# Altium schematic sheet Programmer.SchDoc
size A
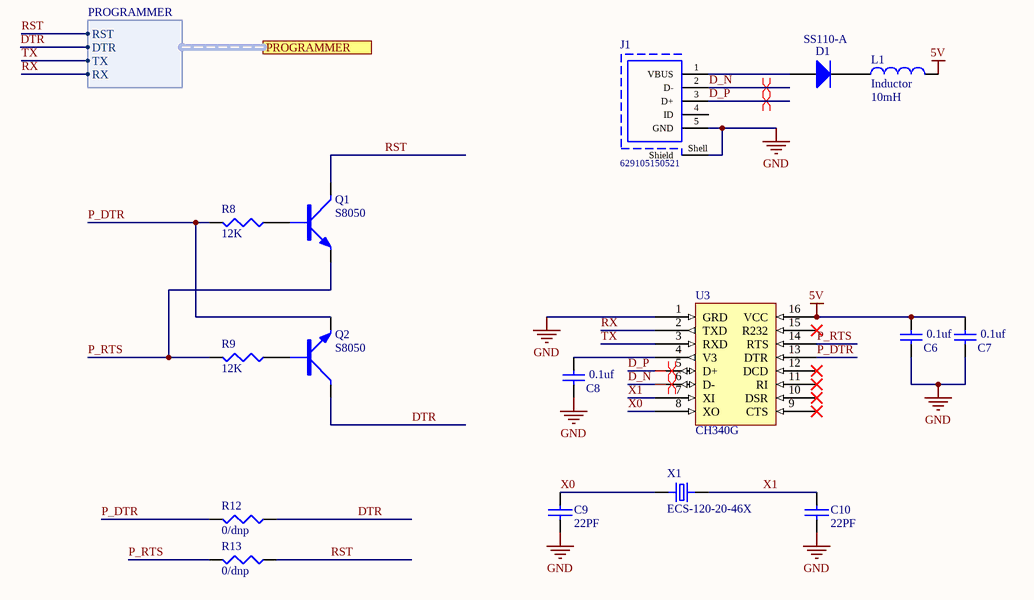
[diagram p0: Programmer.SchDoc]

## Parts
C6  0.1uf  [CAPC0603]
C7  0.1uf  [CAPC0603]
C8  0.1uf  [CAPC0603]
C9  22PF  [CAPC0603]
C10  22PF  [CAPC0603]
D1  SS110-A  [BZT55B13GS08]
J1  629105150521  [629105150521]
L1  Inductor  value 10mH  [CAPC0805]
Q1  S8050  [SOT23-3]
Q2  S8050  [SOT23-3]
R8  12K  [RESC0603]
R9  12K  [RESC0603]
R12  0/dnp  [RESC0603]
R13  0/dnp  [RESC0603]
U3  CH340G  [SOIC16_N]
X1  ECS-120-20-46X  [XTAL_ECS-120-20-46X]

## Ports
PROGRAMMER (harness PROGRAMMER)

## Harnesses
PROGRAMMER: RST, DTR, TX, RX

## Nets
5V: C6.1 C7.1 L1.2 U3.16(VCC)
GND: C6.2 C7.2 C8.2 C9.1 C10.1 J1.5(GND) J1.Shell(Shield) U3.1(GRD)
D_N: J1.2(D-) U3.6(D-)
D_P: J1.3(D+) U3.5(D+)
DTR: Q2.3(COLL) R12.1 ; port PROGRAMMER.DTR
P_DTR: Q2.2(EMIT) R8.2 R12.2 U3.13(DTR)
P_RTS: Q1.2(EMIT) R9.2 R13.2 U3.14(RTS)
RST: Q1.3(COLL) R13.1 ; port PROGRAMMER.RST
RX: U3.2(TXD) ; port PROGRAMMER.RX
TX: U3.3(RXD) ; port PROGRAMMER.TX
X0: C9.2 U3.8(XO) X1.1
X1: C10.2 U3.7(XI) X1.2
NetC8_1: C8.1 U3.4(V3)
NetD1_1: D1.1(A) L1.1
NetD1_2: D1.2(K) J1.1(VBUS)
NetQ1_1: Q1.1(BASE) R8.1
NetQ2_1: Q2.1(BASE) R9.1

Not connected (* = marked no-connect by the designer): J1 4(ID); U3 9(CTS)* 10(DSR)* 11(RI)* 12(DCD)* 15(R232)*

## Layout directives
differential pair: D_N, D_P

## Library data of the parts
C6-C8 = CMP-2007-04765-1: Part Number: 08055C104KAJ2A; Manufacturer: AVX Interconnect / Elco
C9 C10 = CAP NP
D1 = Diode: Default Diode
J1 = CMP-1502-03252-1: Micro USB 2.0 Type B Receptacle WR-COM, Horizontal, SMT, with Pegs, High Current at Pin 1 & Pin 5; Manufacturer: Wurth Elektronik; Contact Resistance: 30mOhm; Rated Current: 3A; Working Voltage: 30VAC
L1 = Inductor: Code_IEC: 1005
Q1 Q2 = NPN BEC
R8 R9 R12 R13 = RES1: RESISTOR
X1 = ECS-120-20-46X: QUARTZ CRYSTAL  T/H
